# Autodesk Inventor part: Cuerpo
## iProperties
Shininess: 64.0
Length Units: 11272
Angle Units: 11279
Time Units: 11290
Mass Units: 11286
Length Display Precision: 3
Angle Display Precision: 2
Compacted: True
Part Number: Cuerpo
Document SubType Name: Modeling
Created: 2005-06
Designer: Alek
Manufacturer: Standard
Standards Organization: Custom
Density: 0.0
Volumn: 0.0
Area: 0.0
PropertySet Name: Model Information
Control State: 0
Master: False
Checked Out: False
Author: Alek
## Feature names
1. Extrusion1
2. Extrusion2
3. Circular Pattern1
4. Mirror1
5. Extrusion3
6. Hole1
7. Hole2
8. Extrusion4
9. Hole3
10. Circular Pattern2
